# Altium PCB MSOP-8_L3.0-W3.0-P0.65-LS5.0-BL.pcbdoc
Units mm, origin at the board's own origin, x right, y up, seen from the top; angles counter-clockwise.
Board outline 16.12 x 18.69 mm, 2 copper layers (Top Layer, Bottom Layer), stack 0 mm thick; 1 components, 0 nets, 8 pads, 0 vias.
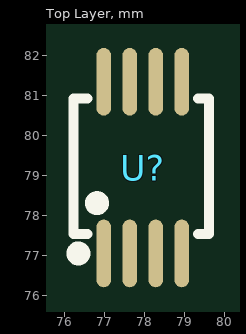
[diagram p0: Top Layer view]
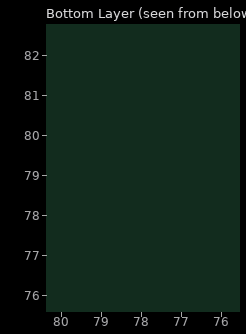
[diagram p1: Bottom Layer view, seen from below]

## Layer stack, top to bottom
Top Layer: signal copper (thickness not stored)
Bottom Layer: signal copper (thickness not stored)

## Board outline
85.968,69.85 69.85,69.85 69.85,88.542 85.968,88.542

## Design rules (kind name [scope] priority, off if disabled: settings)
PasteMaskExpansion "Paste Mask Expansion" [All] p1: expansion=0
SolderMaskExpansion "Solder Mask Expansion" [IsVia] p1: expansion=-25.4 istentingtop=TRUE
SolderMaskExpansion "Solder Mask Expansion" [All] p2: expansion=0.051 istentingtop=FALSE

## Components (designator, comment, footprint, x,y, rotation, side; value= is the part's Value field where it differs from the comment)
U? "" MSOP-8_L3.0-W3.0-P0.65-LS5.0-BL 77.959,79.2 r0 top

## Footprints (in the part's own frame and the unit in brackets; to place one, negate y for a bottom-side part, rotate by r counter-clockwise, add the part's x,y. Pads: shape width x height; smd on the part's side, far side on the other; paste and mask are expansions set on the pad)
MSOP-8_L3.0-W3.0-P0.65-LS5.0-BL [mm]
  oval 0.364x1.692 smd: 1(-0.975,-2.146) 2(-0.325,-2.146) 3(0.325,-2.146) 4(0.975,-2.146) 5(0.975,2.146) 6(0.325,2.146) 7(-0.325,2.146) 8(-0.975,2.146)
  silkscreen extent -1.76,-2.3 1.66,1.73

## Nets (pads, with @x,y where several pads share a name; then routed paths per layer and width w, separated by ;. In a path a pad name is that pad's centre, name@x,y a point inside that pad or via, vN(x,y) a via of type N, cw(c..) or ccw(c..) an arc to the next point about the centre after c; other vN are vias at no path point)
pads on no net: U?.1 U?.2 U?.3 U?.4 U?.5 U?.6 U?.7 U?.8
